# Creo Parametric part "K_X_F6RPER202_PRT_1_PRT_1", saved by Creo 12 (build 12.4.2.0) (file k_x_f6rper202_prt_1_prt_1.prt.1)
Units: Custom; MM, KILOGRAM, SECS

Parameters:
  PTC_WM_ITERATION = "0"
  PTC_WM_VERSION = "-.0"
  PTC_WM_LIFECYCLE_STATE = "In Work"
  PTC_WM_LIFECYCLE = "MO_CADDocument"
  PTC_WM_CREATED_BY = "Maximilian Roepper (Z0017RMS: MO)"
  PTC_WM_CREATED_ON = "18-Sep-26 11:36:42 AM"
  PTC_WM_MODIFIED_BY = "Maximilian Roepper (Z0017RMS: MO)"
  PTC_WM_MODIFIED_ON = "18-Sep-26 11:36:46 AM"
  PDMLINKNUMBER = "PDM000071455187"
  PTC_WM_NAME = "k_x_f6rper202_prt_1_prt_1.prt"
  PTC_WM_NUMBER = "PDM000071455187"

Other parameters: WEIGHT, WEIGHT_FACTOR, WEIGHT_ADD, _MASS_TEMP, _DIFF_TEMP, MC_ERRORS, SUPPLIER

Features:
  1. coordinate system
  2. datum plane "PRT_YZ"
  3. datum plane "PRT_XY"
  4. datum plane "PRT_XZ"
  5. coordinate system
  6. datum axis
  7. datum axis
  8. datum axis
  9. coordinate system
  10. imported feature
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
Other named items: PRT, SIEMENS_MO, DRW_VIEW_ORG, PRT_X, PRT_Y, PRT_Z, CS0, ROUGH_GROB

Layers: 00_STD_CSYS-KSYS, 01_STD_PLANES-EBENEN, 02_STD_AXES-ACHSEN, 03_STD_CSYS-KSYS, 24_IMPORT_FEAT-IMPORT_KE

Surfaces: 13 plane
